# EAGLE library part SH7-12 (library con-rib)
RIBBON CABLE CONNECTOR Flachstecker / Faston
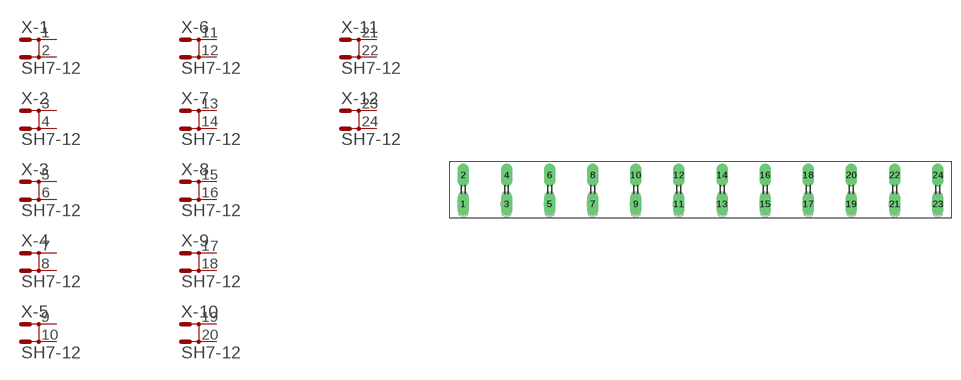
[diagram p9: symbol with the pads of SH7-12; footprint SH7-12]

Designator prefix X; gates -1=MD -2=MD -3=MD -4=MD -5=MD -6=MD -7=MD -8=MD -9=MD -10=MD -11=MD -12=MD

## SH7-12  [SH7-12]
1  -1:1  pas
2  -1:2  pas
3  -2:1  pas
4  -2:2  pas
5  -3:1  pas
6  -3:2  pas
7  -4:1  pas
8  -4:2  pas
9  -5:1  pas
10  -5:2  pas
11  -6:1  pas
12  -6:2  pas
13  -7:1  pas
14  -7:2  pas
15  -8:1  pas
16  -8:2  pas
17  -9:1  pas
18  -9:2  pas
19  -10:1  pas
20  -10:2  pas
21  -11:1  pas
22  -11:2  pas
23  -12:1  pas
24  -12:2  pas

## Footprint SH7-12 (pad centres in mm)
RIBBON CABLE CONNECTOR Flachstecker / Faston
drill 1.321 long: 1 -41.25,-2.515; 2 -41.25,2.515; 3 -33.731,-2.515; 4 -33.731,2.515; 5 -26.238,-2.515; 6 -26.238,2.515; 7 -18.745,-2.515; 8 -18.745,2.515; 9 -11.252,-2.515; 10 -11.252,2.515; 11 -3.759,-2.515; 12 -3.759,2.515; 13 3.759,-2.515; 14 3.759,2.515; 15 11.252,-2.515; 16 11.252,2.515; 17 18.745,-2.515; 18 18.745,2.515; 19 26.238,-2.515; 20 26.238,2.515; 21 33.757,-2.515; 22 33.757,2.515; 23 41.275,-2.515; 24 41.275,2.515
